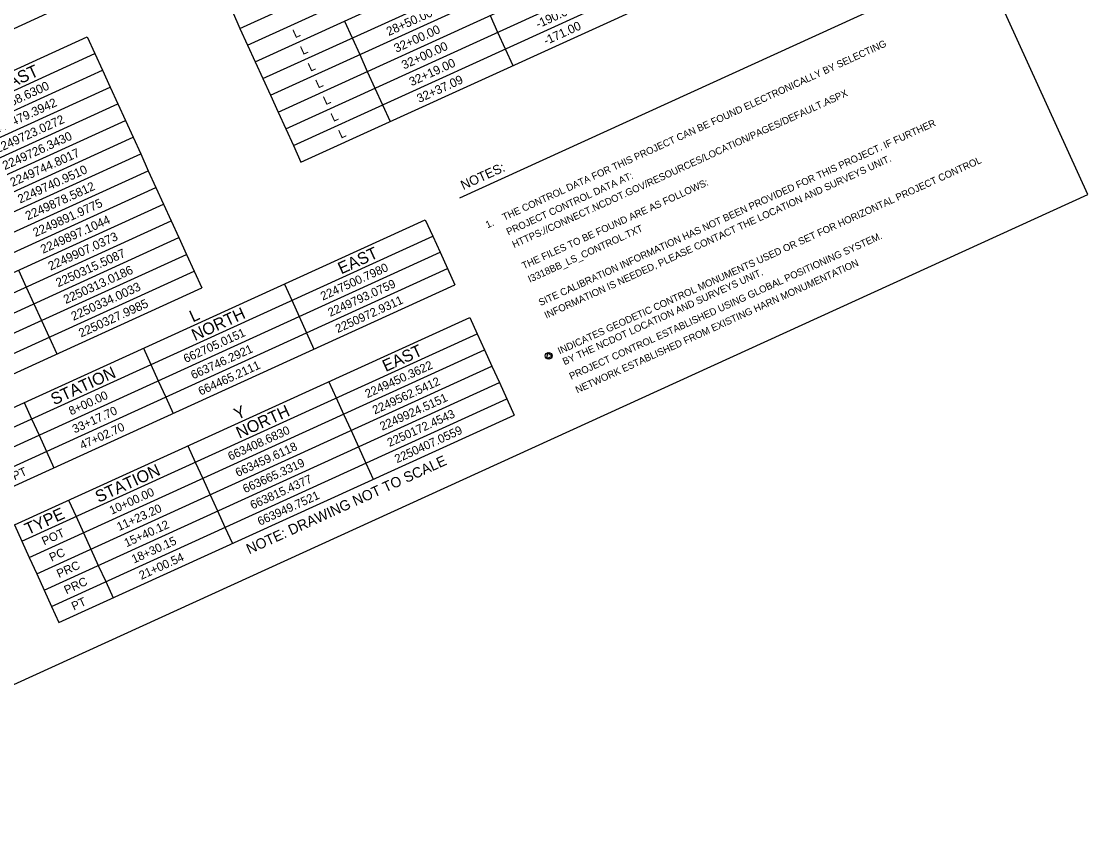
# Model space of a CAD drawing. Extents: x 2253388 to 2258607, y 664121 to 668933.
# Drawn here: x 2255684 to 2258607, y 664381 to 666618 of the extents above; entities that cross this region are included whole.
import ezdxf

# ---------------------------------------------------------------- set-up
doc = ezdxf.new("R2010")
doc.units = 0
for name, color, linetype in [('CTL NGS Horizontal CELL', 7, 'Continuous'), ('CTL Sheet Border CELL', 7, 'Continuous'), ('CTL Sheet Notes CELL', 7, 'Continuous'), ('CTL Sheet Table Cell', 7, 'Continuous'), ('CTL Sheet Text', 7, 'Continuous')]:
    doc.layers.add(name, color=color, linetype=linetype)

# ---------------------------------------------------------------- blocks, each defined once
blk = doc.blocks.new('CTL NGS HORIZONTAL')
at = {"layer": 'CTL NGS Horizontal CELL'}
blk.add_line((0, 0), (0, 0), dxfattribs=at)
blk.add_lwpolyline([(-0.064, -0.037), (0.064, -0.037), (0, 0.074), (-0.064, -0.037)], dxfattribs=at)
blk.add_circle((0, 0), 0.0738, dxfattribs=at)

msp = doc.modelspace()

# ---------------------------------------------------------------- linework, layer by layer
at = {"layer": 'CTL Sheet Border CELL'}
msp.add_lwpolyline([(2257373.5, 668848.7), (2253509.6, 667086.2), (2254743.3, 664381.5), (2258607.2, 666143.9)], close=True, dxfattribs=at)
at = {"layer": 'CTL Sheet Notes CELL'}
msp.add_line((2256885.7, 666134.5), (2258125.1, 666699.8), dxfattribs=at)
at = {"layer": 'CTL Sheet Table Cell'}
for p, q in [((2256283.2, 666599), (2257995.4, 667379.2)), ((2256304.1, 666553.1), (2258016.3, 667333.3)), ((2256325, 666507.3), (2258037.2, 667287.5)), ((2256345.9, 666461.4), (2258058.1, 667241.6)), ((2256366.8, 666415.5), (2258079, 667195.8)), ((2256387.7, 666369.7), (2258099.9, 667149.9)), ((2256408.6, 666323.8), (2258120.8, 667104)), ((2256429.5, 666277.9), (2258141.7, 667058.2)), ((2256450.4, 666232.1), (2258162.6, 667012.3)), ((2254109.3, 665890.3), (2255821.5, 666670.5)), ((2256262.3, 666644.8), (2256283.2, 666599)), ((2256968.7, 666634.4), (2256989.6, 666588.5)), ((2256569.6, 666618.7), (2256590.5, 666572.9)), ((2254152.5, 665795.6), (2255864.7, 666575.8)), ((2255864.7, 666575.8), (2255885.6, 666530)), ((2256283.2, 666599), (2256304.1, 666553.1)), ((2256989.6, 666588.5), (2257010.5, 666542.7)), ((2256304.1, 666553.1), (2256325, 666507.3)), ((2256590.5, 666572.9), (2256611.4, 666527)), ((2254173.4, 665749.7), (2255885.6, 666530)), ((2255885.6, 666530), (2255906.5, 666484.1)), ((2256611.4, 666527), (2256632.3, 666481.1)), ((2257010.5, 666542.7), (2257031.4, 666496.8)), ((2256325, 666507.3), (2256345.9, 666461.4)), ((2254194.3, 665703.9), (2255906.5, 666484.1)), ((2255906.5, 666484.1), (2255927.4, 666438.2)), ((2256345.9, 666461.4), (2256366.8, 666415.5)), ((2256632.3, 666481.1), (2256653.2, 666435.3)), ((2254215.2, 665658), (2255927.4, 666438.2)), ((2255927.4, 666438.2), (2255948.3, 666392.4)), ((2256653.2, 666435.3), (2256674.1, 666389.4)), ((2256366.8, 666415.5), (2256387.7, 666369.7)), ((2254236.1, 665612.2), (2255948.3, 666392.4)), ((2255948.3, 666392.4), (2255969.2, 666346.5)), ((2256674.1, 666389.4), (2256695, 666343.5)), ((2254257, 665566.3), (2255969.2, 666346.5)), ((2255969.2, 666346.5), (2255990.1, 666300.7)), ((2256387.7, 666369.7), (2256408.6, 666323.8)), ((2256408.6, 666323.8), (2256429.5, 666277.9)), ((2254277.9, 665520.4), (2255990.1, 666300.7)), ((2255990.1, 666300.7), (2256011, 666254.8)), ((2254298.8, 665474.6), (2256011, 666254.8)), ((2256011, 666254.8), (2256031.9, 666208.9)), ((2256429.5, 666277.9), (2256450.4, 666232.1)), ((2254319.7, 665428.7), (2256031.9, 666208.9)), ((2256031.9, 666208.9), (2256052.8, 666163.1)), ((2254340.6, 665382.8), (2256052.8, 666163.1)), ((2256052.8, 666163.1), (2256073.7, 666117.2)), ((2254361.5, 665337), (2256073.7, 666117.2)), ((2256073.7, 666117.2), (2256094.6, 666071.3)), ((2254382.4, 665291.1), (2256094.6, 666071.3)), ((2255543, 665505.7), (2256791.2, 666074.5)), ((2256094.6, 666071.3), (2256115.5, 666025.5)), ((2256791.2, 666074.5), (2256811.5, 666029.9)), ((2254403.3, 665245.3), (2256115.5, 666025.5)), ((2255563.3, 665461.1), (2256811.5, 666029.9)), ((2256115.5, 666025.5), (2256136.4, 665979.6)), ((2256811.5, 666029.9), (2256831.9, 665985.3)), ((2254424.2, 665199.4), (2256136.4, 665979.6)), ((2255583.7, 665416.5), (2256831.9, 665985.3)), ((2256136.4, 665979.6), (2256157.3, 665933.8)), ((2256831.9, 665985.3), (2256852.2, 665940.7)), ((2254445.1, 665153.5), (2256157.3, 665933.8)), ((2255604, 665371.9), (2256852.2, 665940.7)), ((2255676.2, 665936.1), (2255697.1, 665890.2)), ((2256157.3, 665933.8), (2256178.2, 665887.9)), ((2256852.2, 665940.7), (2256872.5, 665896.1)), ((2254465.9, 665107.7), (2256178.2, 665887.9)), ((2255624.3, 665327.4), (2256872.5, 665896.1)), ((2255697.1, 665890.2), (2255718, 665844.4)), ((2256404.9, 665898.4), (2256425.2, 665853.8)), ((2256425.2, 665853.8), (2256445.5, 665809.2)), ((2255718, 665844.4), (2255738.9, 665798.5)), ((2255664.9, 665238.2), (2256913.1, 665807)), ((2255738.9, 665798.5), (2255759.8, 665752.6)), ((2256445.5, 665809.2), (2256465.8, 665764.7)), ((2256913.1, 665807), (2256933.4, 665762.4)), ((2255685.2, 665193.6), (2256933.4, 665762.4)), ((2256465.8, 665764.7), (2256486.1, 665720.1)), ((2256933.4, 665762.4), (2256953.7, 665717.8)), ((2255759.8, 665752.6), (2255780.7, 665706.8)), ((2255705.5, 665149), (2256953.7, 665717.8)), ((2256018.5, 665722.4), (2256038.9, 665677.8)), ((2256953.7, 665717.8), (2256974.1, 665673.2)), ((2255725.9, 665104.5), (2256974.1, 665673.2)), ((2256038.9, 665677.8), (2256059.2, 665633.2)), ((2256974.1, 665673.2), (2256994.4, 665628.7)), ((2255746.2, 665059.9), (2256994.4, 665628.7)), ((2256059.2, 665633.2), (2256079.5, 665588.6)), ((2256526.8, 665630.9), (2256547.1, 665586.4)), ((2256994.4, 665628.7), (2257014.7, 665584.1)), ((2255766.5, 665015.3), (2257014.7, 665584.1)), ((2256079.5, 665588.6), (2256099.8, 665544)), ((2256547.1, 665586.4), (2256567.4, 665541.8)), ((2257014.7, 665584.1), (2257035, 665539.5)), ((2255691.6, 665573.4), (2255711.9, 665528.8)), ((2255711.9, 665528.8), (2255732.3, 665484.2)), ((2255786.8, 664970.7), (2257035, 665539.5)), ((2256567.4, 665541.8), (2256587.7, 665497.2)), ((2256587.7, 665497.2), (2256608, 665452.6)), ((2255732.3, 665484.2), (2255752.6, 665439.6)), ((2255752.6, 665439.6), (2255772.9, 665395.1)), ((2256140.4, 665454.9), (2256160.7, 665410.3)), ((2256608, 665452.6), (2256628.3, 665408)), ((2256160.7, 665410.3), (2256181, 665365.7)), ((2256628.3, 665408), (2256648.7, 665363.5)), ((2256181, 665365.7), (2256201.4, 665321.1)), ((2256201.4, 665321.1), (2256221.7, 665276.6)), ((2255813.5, 665305.9), (2255833.8, 665261.3)), ((2255833.8, 665261.3), (2255854.1, 665216.8)), ((2256221.7, 665276.6), (2256242, 665232)), ((2255664.9, 665238.2), (2255685.2, 665193.6)), ((2256242, 665232), (2256262.3, 665187.4)), ((2255854.1, 665216.8), (2255874.5, 665172.2)), ((2255685.2, 665193.6), (2255705.5, 665149)), ((2255705.5, 665149), (2255725.9, 665104.5)), ((2255874.5, 665172.2), (2255894.8, 665127.6)), ((2255894.8, 665127.6), (2255915.1, 665083)), ((2255725.9, 665104.5), (2255746.2, 665059.9)), ((2255746.2, 665059.9), (2255766.5, 665015.3)), ((2255915.1, 665083), (2255935.4, 665038.4)), ((2255766.5, 665015.3), (2255786.8, 664970.7))]:
    msp.add_line(p, q, dxfattribs=at)

# ---------------------------------------------------------------- block references
at = {"layer": 'CTL NGS Horizontal CELL', "xscale": 124.99975000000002, "yscale": 124.99974999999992, "rotation": 24.519065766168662}
msp.add_blockref('CTL NGS HORIZONTAL', (2257129.5, 665701.6), dxfattribs=at)

# ---------------------------------------------------------------- texts
at = {"layer": 'CTL Sheet Border CELL'}
msp.add_text('NOTE: DRAWING NOT TO SCALE', height=28.313, rotation=24.4138, dxfattribs=at).set_placement((2256308.5, 665157.5))
at = {"layer": 'CTL Sheet Notes CELL'}
for s, height, rotation, p in [('1.    THE CONTROL DATA FOR THIS PROJECT CAN BE FOUND ELECTRONICALLY BY SELECTING', 19.37, 24.5191, (2256961.8, 666050.7)), ('EAST', 33.6, 24.4979, (2255627.7, 666421.7)), ('HTTPS://CONNECT.NCDOT.GOV/RESOURCES/LOCATION/PAGES/DEFAULT.ASPX', 19.37, 24.5191, (2257034.7, 665996.7)), ('SITE CALIBRATION INFORMATION HAS NOT BEEN PROVIDED FOR THIS PROJECT. IF FURTHER', 19.37, 24.5191, (2257107.1, 665837.9)), ('NOTES:', 25.83, 24.4138, (2256895.4, 666155.8)), ('INFORMATION IS NEEDED, PLEASE CONTACT THE LOCATION AND SURVEYS UNIT.', 19.37, 24.5191, (2257123, 665803.1)), ('INDICATES GEODETIC CONTROL MONUMENTS USED OR SET FOR HORIZONTAL PROJECT CONTROL', 19.37, 24.4138, (2257159.7, 665705.3)), ('PROJECT CONTROL DATA AT:', 19.37, 24.5191, (2257018.8, 666031.6)), ('THE FILES TO BE FOUND ARE AS FOLLOWS:', 19.37, 24.5191, (2257061.3, 665938.4)), ('I3318BB_LS_CONTROL.TXT', 19.37, 24.5191, (2257078, 665901.8)), ('PROJECT CONTROL ESTABLISHED USING GLOBAL POSITIONING SYSTEM.', 19.37, 24.4138, (2257191.2, 665635.9)), ('EAST', 32.66, 24.4979, (2256560.9, 665924.6)), ('NETWORK ESTABLISHED FROM EXISTING HARN MONUMENTATION', 19.37, 24.4138, (2257208.2, 665598.6)), ('BY THE NCDOT LOCATION AND SURVEYS UNIT.', 19.37, 24.4138, (2257173, 665675.9)), ('L', 32.7, 24.4979, (2256153.9, 665793)), ('NORTH', 32.66, 24.4979, (2256159.8, 665741.9)), ('EAST', 32.66, 24.4979, (2256682.8, 665657.2)), ('STATION', 32.66, 24.4979, (2255773.7, 665565.9)), ('Y', 32.7, 24.4979, (2256275.8, 665525.5)), ('NORTH', 32.66, 24.4979, (2256281.7, 665474.4)), ('STATION', 32.66, 24.4979, (2255895.6, 665298.5)), ('TYPE', 32.66, 24.4979, (2255702.1, 665210.3))]:
    msp.add_text(s, height=height, rotation=rotation, dxfattribs=at).set_placement(p)
at = {"layer": 'CTL Sheet Text'}
for s, height, p in [('-190.00', 24, (2257100.9, 666598.4)), ('28+50.00', 24, (2256691.1, 666577.8)), ('32+00.00', 24, (2256712, 666531.9)), ('-171.00', 24, (2257121.8, 666552.5)), ('L', 24, (2256434.6, 666571.7)), ('L', 24, (2256455.5, 666525.8)), ('32+00.00', 24, (2256732.9, 666486.1)), ('L', 24, (2256476.4, 666480)), ('32+19.00', 24, (2256753.8, 666440.2)), ('32+37.09', 24, (2256774.7, 666394.3)), ('2249458.6300', 24, (2255575.9, 666348)), ('L', 24, (2256497.3, 666434.1)), ('2249479.3942', 24, (2255596.8, 666302.1)), ('L', 24, (2256518.2, 666388.3)), ('2249723.0272', 24, (2255617.7, 666256.2)), ('L', 24, (2256539.1, 666342.4)), ('2249726.3430', 24, (2255638.6, 666210.4)), ('L', 24, (2256560, 666296.5)), ('2249744.8017', 24, (2255659.5, 666164.5)), ('2249740.9510', 24, (2255680.4, 666118.7)), ('2249878.5812', 24, (2255701.3, 666072.8)), ('2249891.9775', 24, (2255722.2, 666026.9)), ('2249897.1044', 24, (2255743.1, 665981.1)), ('2249907.0373', 24, (2255764, 665935.2)), ('2250315.5087', 24, (2255784.9, 665889.3)), ('2250313.0186', 24, (2255805.8, 665843.5)), ('2247500.7980', 23.328, (2256510.5, 665853)), ('2249793.0759', 23.328, (2256530.8, 665808.4)), ('2250334.0033', 24, (2255826.7, 665797.6)), ('2250327.9985', 24, (2255847.6, 665751.7)), ('2250972.9311', 23.328, (2256551.1, 665763.8)), ('662705.0151', 23.328, (2256134.7, 665681.7)), ('663746.2921', 23.328, (2256155, 665637.1)), ('664465.2111', 23.328, (2256175.3, 665592.6)), ('2249450.3622', 23.328, (2256632.4, 665585.5)), ('2249562.5412', 23.328, (2256652.7, 665540.9)), ('8+00.00', 23.33, (2255820.2, 665538.4)), ('2249924.5151', 23.328, (2256673, 665496.3)), ('33+17.70', 23.33, (2255830, 665489)), ('2250172.4543', 23.328, (2256693.3, 665451.8)), ('47+02.70', 23.33, (2255850.3, 665444.4)), ('663408.6830', 23.328, (2256256.6, 665414.2)), ('2250407.0559', 23.328, (2256713.6, 665407.2)), ('663459.6118', 23.328, (2256276.9, 665369.7)), ('663665.3319', 23.328, (2256297.2, 665325.1)), ('PT ', 23.33, (2255665.2, 665360.1)), ('663815.4377', 23.328, (2256317.5, 665280.5)), ('10+00.00', 23.33, (2255931.5, 665266.1)), ('663949.7521', 23.328, (2256337.8, 665235.9)), ('11+23.20', 23.33, (2255951.9, 665221.5)), ('15+40.12', 23.33, (2255972.2, 665177)), ('POT', 23.33, (2255746.4, 665181.8)), ('18+30.15', 23.33, (2255992.5, 665132.4)), ('PC ', 23.33, (2255766.8, 665137.2)), ('21+00.54', 23.33, (2256012.8, 665087.8)), ('PRC', 23.33, (2255787.1, 665092.6)), ('PRC', 23.33, (2255807.4, 665048)), ('PT ', 23.33, (2255827.7, 665003.5))]:
    msp.add_text(s, height=height, rotation=24.4979, dxfattribs=at).set_placement(p)

doc.saveas('drawing.dxf')
